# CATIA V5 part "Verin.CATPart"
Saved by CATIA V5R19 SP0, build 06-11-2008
Part number: Verin
Bounding box of the stored display mesh (mm): x -118 to 100, y -13.885 to 13.885, z -13.885 to 13.885
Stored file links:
  G:\EU_thinkMotion\CFAO_2010\St2M_groupe2\St2M_groupe2\csayed\csayed\csayed\Verin.CATPart
  G:\EU_thinkMotion\CFAO_2010\St2M_groupe2\St2M_groupe2\csayed\csayed\csayed\Assemblage.CATProduct
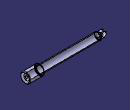
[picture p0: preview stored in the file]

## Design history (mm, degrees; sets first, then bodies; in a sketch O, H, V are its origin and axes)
Body1 (main body)
  Sketch1 on xy-plane, origin (0, 0, 0), H (1, 0, 0), V (0, 1, 0)
    line L1 (-100, 10) -> (60, 10)
    line L2 (60, 10) -> (60, 14)
    point P3 (60, 14)
    line L3 (60, 14) -> (100, 14)
    point P4 (100, 14)
    line L4 (-100, 10) -> (-100, 0)
    point P5 (-100, 0)
    line L5 (-98, 0) -> (-98, 8)
    point P6 (-98, 0)
    point P7 (-98, 8)
    line L6 (-98, 8) -> (96, 8)
    point P8 (96, 8)
    line L7 (96, 8) -> (96, 3)
    point P9 (96, 3)
    line L8 (96, 3) -> (100, 3)
    line L9 (100, 3) -> (100, 14)
    distance P3 H = 14
    distance P4 V = 100
    distance P6 V = 98
    distance P7 H = 8
    distance P8 V = 96
    distance P9 H = 3
    horizontal: L1 H, L3 H, L6 H, L8 H
    vertical: L2 V, L4 V, L5 V, L7 V, L9 V
    coincidence: P5 H, P6 H
  Shaft1: profile Sketch1, axis Sketch1.H, angle 360
  Sketch2 on face of Shaft1 from Sketch1.L4, origin (-100, 0, 0), H (0, -1, 0), V (0, 0, 1)
    line L1 (-4, 7.5) -> (4, 7.5)
    line L2 (4, 7.5) -> (4, -7.5)
    line L3 (4, -7.5) -> (-4, -7.5)
    line L4 (-4, -7.5) -> (-4, 7.5)
    horizontal: L1 H, L3 H
    vertical: L2 V, L4 V
  Pad1: profile Sketch2, direction (-1, 0, 0), length 18
  Fillet1: radius 7, on edge [face of Pad1 from Sketch2.L1 | end face of Pad1]; edge [face of Pad1 from Sketch2.L3 | end face of Pad1]
  Sketch3 on face of Pad1 from Sketch2.L4, origin (0, 4, 0), H (-1, 0, 0), V (0, 0, 1)
    circle A1 centre (108.042, 0) radius 4
    point P1 (108.042, 0)
    point P2 (112.042, 0)
    reference projected line E1 (100, -7.5) -> (118, -7.5) from edge [face of Pad1 from Sketch2.L3 | face of Pad1 from Sketch2.L4]
    reference projected arc E2 centre (111, -0.5) radius 7 from (111, -7.5) to (118, -0.5) ccw from edge [face of Pad1 from Sketch2.L4 | face of Fillet1]
    distance P1 E1 = 7.5
    distance P1 E2 = 10
    coincidence: A1 P2, P2 H
  Pocket1: profile Sketch3, direction (0, -1, 0), through (limit type 3)
  Chamfer1: length 1, angle 45, on edge [face of Shaft1 from Sketch1.L2 | face of Shaft1 from Sketch1.L1]
  Fillet2: radius 1, on edge [face of Shaft1 from Sketch1.L3 | face of Shaft1 from Sketch1.L2]
  Fillet3: radius 1, on edge [face of Shaft1 from Sketch1.L1 | face of Shaft1 from Sketch1.L4]
  Fillet4: radius 2, on edge [face of Shaft1 from Sketch1.L9 | face of Shaft1 from Sketch1.L3]
  Split1: SplitPlane face of Shaft1 from Sketch1.L1
  Sketch4 on face of Shaft1 from Sketch1.L4, origin (-100, 0, 0), H (0, -1, 0), V (0, 0, 1)
    line L1 (-4, 6) -> (4, 6)
    line L2 (4, 6) -> (4, -6)
    line L3 (4, -6) -> (-4, -6)
    line L4 (-4, -6) -> (-4, 6)
    length L2 = 12
    length L3 = 8
    horizontal: L1 H, L3 H
    vertical: L2 V, L4 V
  Pad2: profile Sketch4, direction (-1, 0, 0), length 13
  Sketch5 on face of Pad2 from Sketch4.L4, origin (0, 4, 0), H (-1, 0, 0), V (0, 0, 1)
    circle A1 centre (106.6076, -0.0344) radius 3
  Pocket2: profile Sketch5, direction (0, -1, 0), length 13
